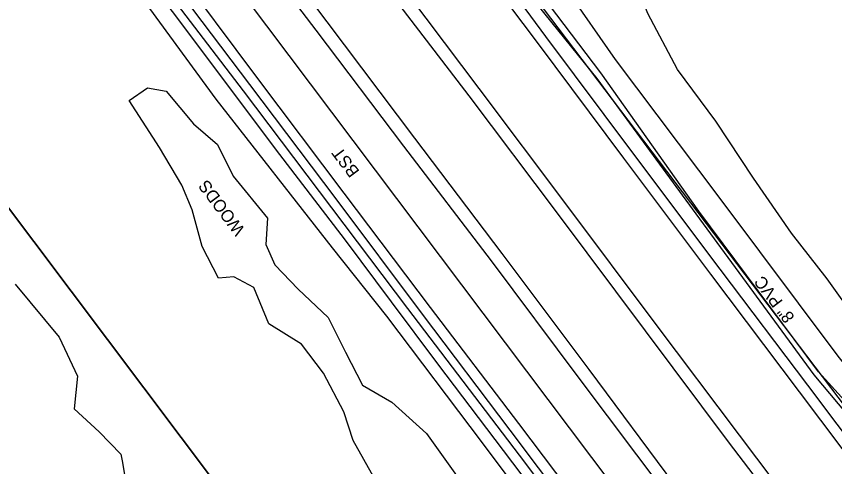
# Model space of a CAD drawing. Extents: x 1262092 to 1264624, y 774970 to 778314.
# Drawn here: x 1262432.5 to 1262699.3, y 777525 to 777671.7 of the extents above; entities that cross this region are included whole.
import ezdxf

# ---------------------------------------------------------------- set-up
doc = ezdxf.new("R2010")
doc.units = 0
for name, color, linetype in [('Exist Boundary City Limits', 7, 'Continuous'), ('Exist Horizontal Alignment', 7, 'Continuous'), ('Exist Right of Way Line', 7, 'Continuous'), ('Exist Roads EOP', 7, 'Continuous'), ('Exist Roads EOT', 7, 'Continuous'), ('Exist Utilities Gas UG Line SUE LOS B', 7, 'Continuous'), ('Exist Utilities Sanitary Sewer UG Line', 7, 'Continuous'), ('Exist Utilities Sanitary Sewer UG Line Text', 7, 'Continuous'), ('Exist Utilities Telephone UG FO SUE LOS B', 7, 'Continuous'), ('Exist Utilities Water UG Line SUE LOS B', 7, 'Continuous'), ('Exist Vegetation Woods Line Text', 7, 'Continuous'), ('Prop Conc 5in Monolithic Keyed In Island', 7, 'Continuous'), ('Prop Horizontal Alignment', 7, 'Continuous'), ('Typical Text Label CELL', 7, 'Continuous')]:
    doc.layers.add(name, color=color, linetype=linetype)

msp = doc.modelspace()

# ---------------------------------------------------------------- linework, layer by layer
at = {"layer": 'Exist Boundary City Limits'}
msp.add_line((1263013.39, 776834.66), (1262172.78, 777950.69), dxfattribs=at)
at = {"layer": 'Exist Horizontal Alignment'}
msp.add_line((1264460.35, 775084.79), (1262255.05, 778012.66), dxfattribs=at)
at = {"layer": 'Exist Right of Way Line'}
msp.add_line((1262172.78, 777950.69), (1263224.83, 776553.94), dxfattribs=at)
at = {"layer": 'Exist Roads EOP'}
for points in [[(1262982.53, 777073.82), (1262955.55, 777109.3), (1262928.42, 777145.56), (1262900.69, 777182.74), (1262872.34, 777220.82), (1262844.32, 777257.6), (1262815.63, 777295.35), (1262787.99, 777332.27), (1262760.77, 777368.27), (1262732.29, 777406.26), (1262703.53, 777444.22), (1262703.55, 777444.2), (1262675.64, 777481.25), (1262647.24, 777519.05), (1262619.25, 777556.57), (1262590.88, 777594.45), (1262562.41, 777631.96), (1262533.86, 777669.85), (1262506.16, 777706.68)], [(1262581.77, 777696.76), (1262605.02, 777665.12), (1262633.36, 777627.24), (1262661.91, 777589.34), (1262690.46, 777551.49), (1262719.22, 777513.4), (1262746.97, 777476.08), (1262773.62, 777440.76), (1262802.75, 777402.21), (1262831.32, 777364.09), (1262858.19, 777328.14), (1262886.09, 777290.94), (1262913.38, 777255.47), (1262941.92, 777217.23), (1262974.58, 777174.56)], [(1262930.86, 777089.4), (1262902.71, 777126.43), (1262875.01, 777163.54), (1262846.68, 777201.15), (1262818.83, 777237.2), (1262790.81, 777274.63), (1262762.38, 777312.81), (1262734.99, 777348.79), (1262707.23, 777385.88), (1262678.03, 777424.58), (1262678.1, 777424.6), (1262649.57, 777462.36), (1262621.56, 777499.63), (1262593.49, 777536.82), (1262564.97, 777574.69), (1262536.79, 777612.19), (1262508.59, 777649.5), (1262480.62, 777686.61)], [(1262551.17, 777683.56), (1262580.06, 777645.73), (1262608.84, 777607.53), (1262637.53, 777569.2), (1262664.94, 777532.66), (1262692.64, 777496.32), (1262720.62, 777458.91), (1262748.48, 777421.14), (1262777.36, 777382.85), (1262804.87, 777346.49), (1262832.58, 777309.22), (1262861.34, 777271.61), (1262889.26, 777234.57), (1262918.02, 777196.13), (1262945.71, 777159.53), (1262972.54, 777124.15), (1262999.26, 777088.5)]]:
    msp.add_lwpolyline(points, dxfattribs=at)
at = {"layer": 'Exist Roads EOT'}
for points in [[(1262979.34, 777071.55), (1262952.73, 777106.88), (1262925.27, 777143.52), (1262897.25, 777180.33), (1262868.7, 777218.05), (1262841.03, 777254.71), (1262812.09, 777292.76), (1262784.33, 777329.52), (1262756.93, 777366.26), (1262729.04, 777403.83), (1262700.43, 777442.05), (1262700.42, 777442.08), (1262672.68, 777478.81), (1262644.08, 777516.56), (1262615.98, 777553.77), (1262587.41, 777591.99), (1262558.81, 777629.41), (1262530.21, 777667.14), (1262502.53, 777703.54)], [(1262573.92, 777700.82), (1262602.3, 777663.12), (1262630.46, 777625.47), (1262658.86, 777587.71), (1262687.81, 777549.36), (1262715.91, 777512.01), (1262744.26, 777474.24), (1262770.57, 777439.41), (1262799.73, 777400.38), (1262828.22, 777362.56), (1262855.35, 777326.32), (1262883.21, 777289.28), (1262910.68, 777252.94), (1262938.99, 777215.45), (1262967.77, 777177.08), (1262994.46, 777141.54), (1263021.73, 777105.43)], [(1262933.46, 777091.49), (1262905.72, 777128.55), (1262877.63, 777165.57), (1262849.13, 777203), (1262821.64, 777239.58), (1262793.48, 777276.64), (1262765, 777314.68), (1262737.64, 777351.02), (1262709.57, 777388.53), (1262680.86, 777426.61), (1262652.4, 777464.54), (1262624.47, 777501.81), (1262596.33, 777538.99), (1262567.58, 777576.78), (1262539.34, 777614.06), (1262511.28, 777651.42), (1262483.32, 777688.89)], [(1262554.72, 777686.15), (1262583.3, 777648.11), (1262611.88, 777610.15), (1262640.7, 777571.7), (1262668.16, 777535.24), (1262695.77, 777498.64), (1262723.78, 777461.2), (1262751.96, 777423.82), (1262781.01, 777385.34), (1262781, 777385.31), (1262808.32, 777349.17), (1262836.1, 777312), (1262864.5, 777274.02), (1262892.16, 777237.27), (1262921.03, 777198.81), (1262948.88, 777161.95), (1262975.45, 777126.54), (1263002.46, 777090.67)]]:
    msp.add_lwpolyline(points, dxfattribs=at)
at = {"layer": 'Exist Utilities Gas UG Line SUE LOS B'}
msp.add_lwpolyline([(1262994.39, 777166.73), (1262980.63, 777180.77), (1262951.12, 777219.34), (1262915.77, 777266.99), (1262883.3, 777310), (1262857.54, 777344.34), (1262828.14, 777381.91), (1262793.47, 777427.19), (1262760.54, 777472.85), (1262727.33, 777519.3), (1262694.08, 777555.83), (1262655.09, 777608.15), (1262623.1, 777653.3), (1262592.34, 777693.87), (1262575.48, 777722.21), (1262534.9, 777775.61), (1262497.72, 777820.92), (1262460.79, 777868.95), (1262430.33, 777909.82), (1262335.35, 778033.97), (1262366.66, 777994.16), (1262337.19, 778032.97), (1262314.26, 778062.88)], dxfattribs=at)
msp.add_lwpolyline([(1262994.39, 777166.73), (1262980.63, 777180.77), (1262951.12, 777219.34), (1262915.77, 777266.99), (1262883.3, 777310), (1262857.54, 777344.34), (1262828.14, 777381.91), (1262793.47, 777427.19), (1262760.54, 777472.85), (1262727.33, 777519.3), (1262694.08, 777555.83), (1262655.09, 777608.15), (1262623.1, 777653.3), (1262592.34, 777693.87), (1262575.48, 777722.21), (1262534.9, 777775.61), (1262497.72, 777820.92), (1262460.79, 777868.95), (1262430.33, 777909.82), (1262335.35, 778033.97), (1262366.66, 777994.16), (1262337.19, 778032.97), (1262314.26, 778062.88)], dxfattribs=at)
at = {"layer": 'Exist Utilities Sanitary Sewer UG Line'}
msp.add_line((1263142.14, 776964.69), (1262537.27, 777762.91), dxfattribs=at)
at = {"layer": 'Exist Utilities Telephone UG FO SUE LOS B'}
for points in [[(1262989.94, 777168.07), (1262951.99, 777219.94), (1262916.42, 777267.81), (1262888.77, 777316.31), (1262864.92, 777351.47), (1262838.91, 777387.68), (1262799.61, 777432.02), (1262765.27, 777476.73), (1262731.32, 777522.28), (1262700.44, 777560.94), (1262661.97, 777612.3), (1262627.92, 777657.64), (1262612.11, 777680.33), (1262604.08, 777687.9), (1262594.67, 777695.7), (1262574.71, 777722.66), (1262534.65, 777775.25), (1262499.34, 777822.06), (1262462.07, 777869.42), (1262431.13, 777910.63), (1262336.58, 778034.92), (1262368.35, 777994.88), (1262338.32, 778033.37), (1262315.72, 778063.86)], [(1262989.94, 777168.07), (1262951.99, 777219.94), (1262916.42, 777267.81), (1262888.77, 777316.31), (1262864.92, 777351.47), (1262838.91, 777387.68), (1262799.61, 777432.02), (1262765.27, 777476.73), (1262731.32, 777522.28), (1262700.44, 777560.94), (1262661.97, 777612.3), (1262627.92, 777657.64), (1262612.11, 777680.33), (1262604.08, 777687.9), (1262594.67, 777695.7), (1262574.71, 777722.66), (1262534.65, 777775.25), (1262499.34, 777822.06), (1262462.07, 777869.42), (1262431.13, 777910.63), (1262336.58, 778034.92), (1262368.35, 777994.88), (1262338.32, 778033.37), (1262315.72, 778063.86)], [(1262982.78, 777167.11), (1262946.46, 777216.4), (1262911.63, 777263.89), (1262904.55, 777273.66), (1262904.75, 777279.08), (1262882.68, 777309.56), (1262855.72, 777342.59), (1262826.17, 777380.64), (1262792.14, 777426.47), (1262758.72, 777471.04), (1262724.36, 777517.1), (1262692.7, 777554.83), (1262654.13, 777607.32), (1262621.89, 777651.43), (1262589.79, 777691.14), (1262572.86, 777709.66), (1262527.82, 777770.05), (1262493.25, 777818.33), (1262456.6, 777866.38), (1262426.24, 777906.46), (1262391.81, 777952.18), (1262362.73, 777991.03), (1262332.92, 778030.12), (1262309.95, 778059.98)], [(1262910.35, 777090.71), (1262890.34, 777118.27), (1262865.78, 777158.05), (1262838.45, 777189.77), (1262811.38, 777217.63), (1262774.04, 777266.39), (1262739.96, 777320.46), (1262735.6, 777333.52), (1262715.57, 777355.48), (1262686.67, 777396.44), (1262655.65, 777437.37), (1262635.3, 777465.04), (1262584.48, 777532.7), (1262553.29, 777574), (1262535.57, 777596.2), (1262497.69, 777644.72), (1262472.81, 777678.82)]]:
    msp.add_lwpolyline(points, dxfattribs=at)
at = {"layer": 'Exist Utilities Water UG Line SUE LOS B'}
msp.add_lwpolyline([(1262961.53, 777041.32), (1262916.91, 777099.45), (1262892.75, 777131.3), (1262862.6, 777171.1), (1262817.98, 777226.85), (1262789.55, 777268.74), (1262774.27, 777287.66), (1262763.83, 777305.05), (1262732.33, 777346.94), (1262685.88, 777410.11), (1262660.87, 777443.18), (1262632.31, 777481.08), (1262598.3, 777526.4), (1262560.14, 777576.52), (1262506.51, 777647.45), (1262479.01, 777683.48), (1262453.07, 777718.25), (1262416.94, 777766.02), (1262382.77, 777811.78), (1262358.61, 777844.73), (1262327.38, 777885.68), (1262302.32, 777918.54), (1262259.45, 777971.43), (1262223.66, 778020.3)], dxfattribs=at)
at = {"layer": 'Prop Conc 5in Monolithic Keyed In Island'}
for points in [[(1262828.02, 777411.4), (1262816.5, 777423.83), (1262806.71, 777431.19), (1262790.41, 777447.23), (1262777.65, 777467.4), (1262769.31, 777484.33), (1262763.08, 777498.85), (1262752.07, 777510.27), (1262737.35, 777527.97), (1262725.97, 777538.12), (1262719.22, 777551.45), (1262706.42, 777572.84), (1262696.89, 777586.18), (1262685.28, 777601.08), (1262672.87, 777618.92), (1262660.56, 777637.56), (1262648.1, 777654.39), (1262638.42, 777672.62), (1262634.06, 777683.75), (1262627.32, 777695.3), (1262623.86, 777706.76), (1262618.99, 777719.73), (1262612.38, 777731.46), (1262607.52, 777734.64)], [(1262552.77, 777514.91), (1262542.28, 777533.51), (1262539.23, 777542.78), (1262532.65, 777555.43), (1262525.47, 777564.86), (1262514.87, 777571.51), (1262509.89, 777583.33), (1262503.43, 777586.79), (1262498.4, 777586.36), (1262493.07, 777596.66), (1262489.87, 777608.59), (1262486.41, 777616.66), (1262479.21, 777628.93), (1262469.3, 777644.3), (1262475.22, 777648.36), (1262481.4, 777647.27), (1262490.25, 777636.7), (1262498.04, 777629.97), (1262503.17, 777619.6), (1262514.38, 777605.92), (1262513.81, 777597.29), (1262516.77, 777590.71), (1262524.41, 777582.78), (1262534.19, 777573.55), (1262539.81, 777562.31), (1262545.38, 777551.47), (1262554.91, 777545.97), (1262566.24, 777535.78), (1262576.59, 777521.35)], [(1262432.1, 777584.42), (1262446.41, 777567.13), (1262452.39, 777554.47), (1262451.3, 777543.83), (1262459.5, 777536.34), (1262466.61, 777528.99), (1262466.98, 777526.86), (1262470.5, 777506.18)]]:
    msp.add_lwpolyline(points, dxfattribs=at)
at = {"layer": 'Typical Text Label CELL'}
msp.add_lwpolyline([(1262768.2, 777292.26), (1262757.43, 777308.58), (1262750.97, 777317.87), (1262727.73, 777348.88), (1262712, 777369.55), (1262697.36, 777389.13), (1262675.04, 777418.88), (1262656.25, 777443.92), (1262630.05, 777478.82), (1262611.34, 777503.87), (1262588.61, 777533.8), (1262569.91, 777558.5), (1262554.82, 777578.68), (1262539.79, 777598.72), (1262516.99, 777628.51), (1262502.14, 777648.38), (1262483.36, 777673.29), (1262468.18, 777693.3), (1262449.46, 777718.32)], dxfattribs=at)

# ---------------------------------------------------------------- texts
at = {"layer": 'Exist Utilities Sanitary Sewer UG Line Text'}
msp.add_text('8" PVC', height=4, rotation=127.1538, dxfattribs=at).set_placement((1262686.46, 777573.69))
at = {"layer": 'Exist Vegetation Woods Line Text'}
msp.add_text('WOODS', height=4, rotation=126.9874, dxfattribs=at).set_placement((1262507.26, 777602.15))
at = {"layer": 'Prop Horizontal Alignment'}
msp.add_text('BST', height=4, rotation=126.9874, dxfattribs=at).set_placement((1262544.56, 777621.16))
msp.add_text('BST', height=4, rotation=126.9874, dxfattribs=at).set_placement((1262544.56, 777621.16))

doc.saveas('drawing.dxf')
